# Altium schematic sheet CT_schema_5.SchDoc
size 369 x 336 mm
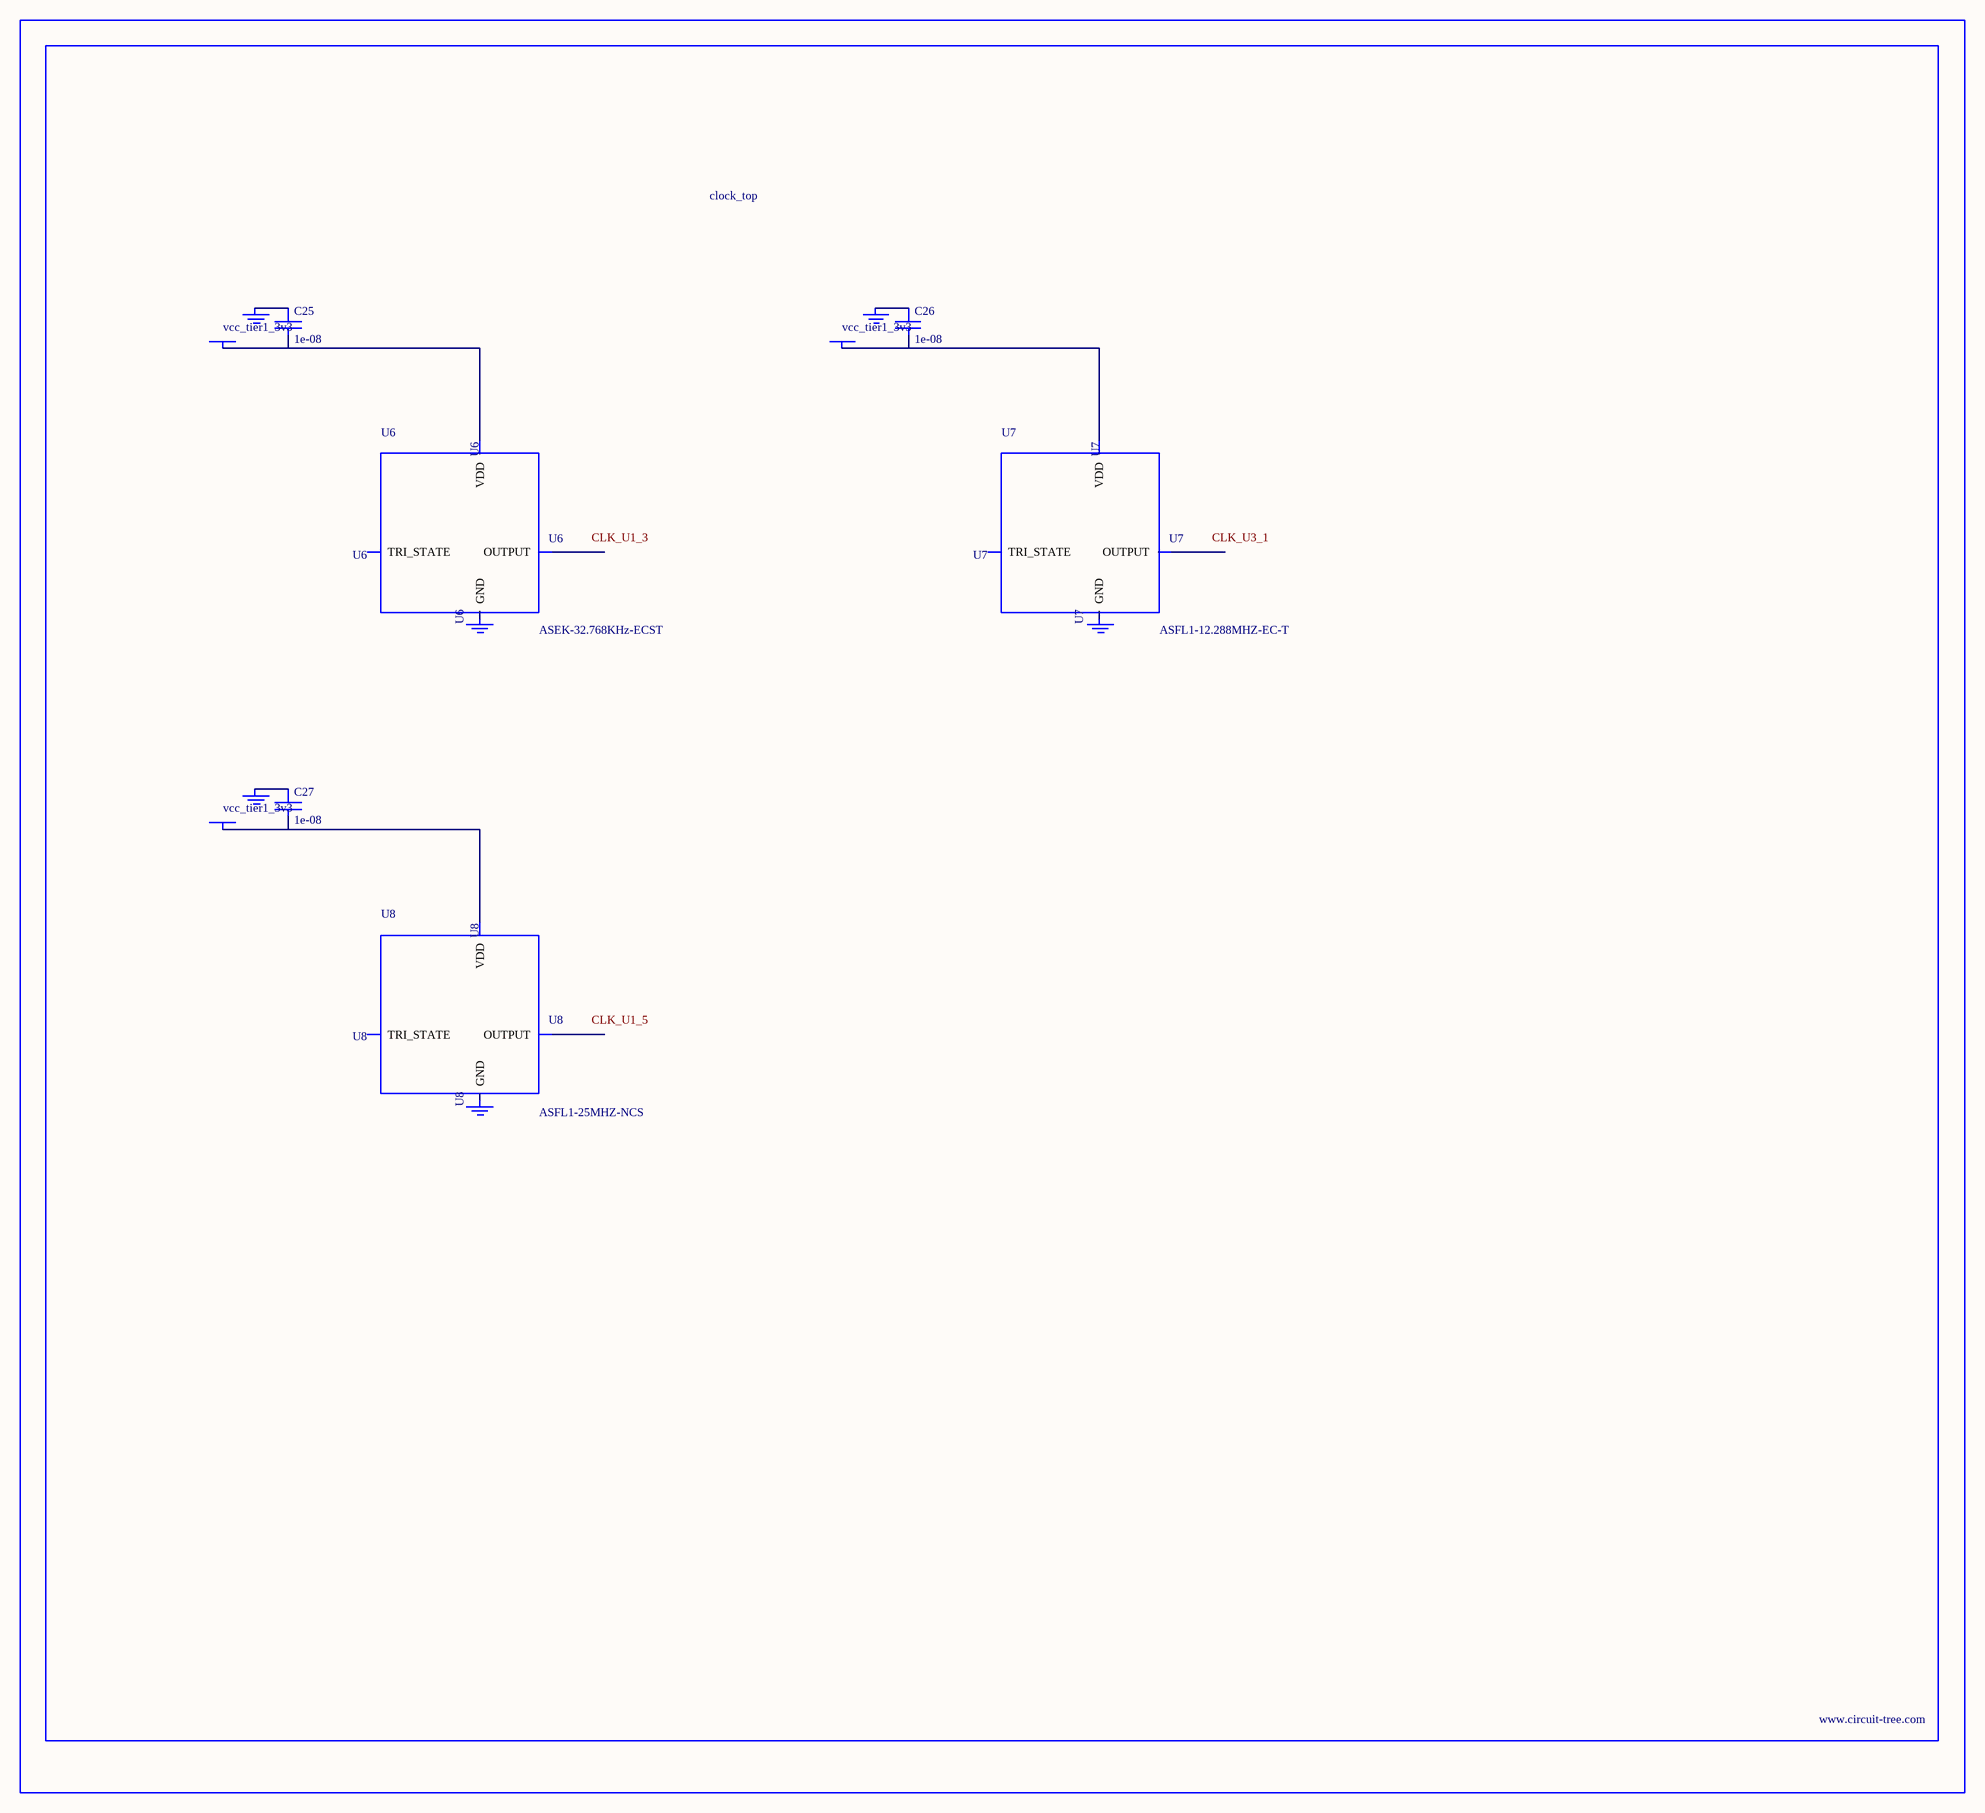
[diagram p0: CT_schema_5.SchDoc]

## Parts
BORDER4  (no value)
C25  1e-08  [C0402]
C26  1e-08  [C0402]
C27  1e-08  [C0402]
GND_INSTANCE_4_0  (no value)
GND_INSTANCE_4_1  (no value)
GND_INSTANCE_4_2  (no value)
GND_INSTANCE_4_3  (no value)
GND_INSTANCE_4_4  (no value)
GND_INSTANCE_4_5  (no value)
POWER_INSTANCE_4_0  vcc_tier1_3v3
POWER_INSTANCE_4_1  vcc_tier1_3v3
POWER_INSTANCE_4_2  vcc_tier1_3v3
U6  ASEK-32.768KHz-ECST  [ASEK]
U7  ASFL1-12.288MHZ-EC-T  [ASFL1]
U8  ASFL1-25MHZ-NCS  [ASFL1]

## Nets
NetC25_1: C25.1 GND_INSTANCE_4_0.0(GND)
NetC25_2: C25.2 POWER_INSTANCE_4_0.0(PWR) U6.4(VDD)
NetC26_1: C26.1 GND_INSTANCE_4_2.0(GND)
NetC26_2: C26.2 POWER_INSTANCE_4_1.0(PWR) U7.4(VDD)
NetC27_1: C27.1 GND_INSTANCE_4_4.0(GND)
NetC27_2: C27.2 POWER_INSTANCE_4_2.0(PWR) U8.4(VDD)

Not connected (* = marked no-connect by the designer): GND_INSTANCE_4_1 0(GND); GND_INSTANCE_4_3 0(GND); GND_INSTANCE_4_5 0(GND); U6 1(TRI_STATE) 2(GND) 3(OUTPUT); U7 1(TRI_STATE) 2(GND) 3(OUTPUT); U8 1(TRI_STATE) 2(GND) 3(OUTPUT)

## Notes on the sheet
- Labels drawn without touching a wire or pin: CLK_U1_3, CLK_U1_5, CLK_U3_1

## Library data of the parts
BORDER4 = BORDER_PAGE4
C25-C27 = C0402C103K3RAC
GND_INSTANCE_4_0-GND_INSTANCE_4_5 = GND
POWER_INSTANCE_4_0-POWER_INSTANCE_4_2 = PWR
